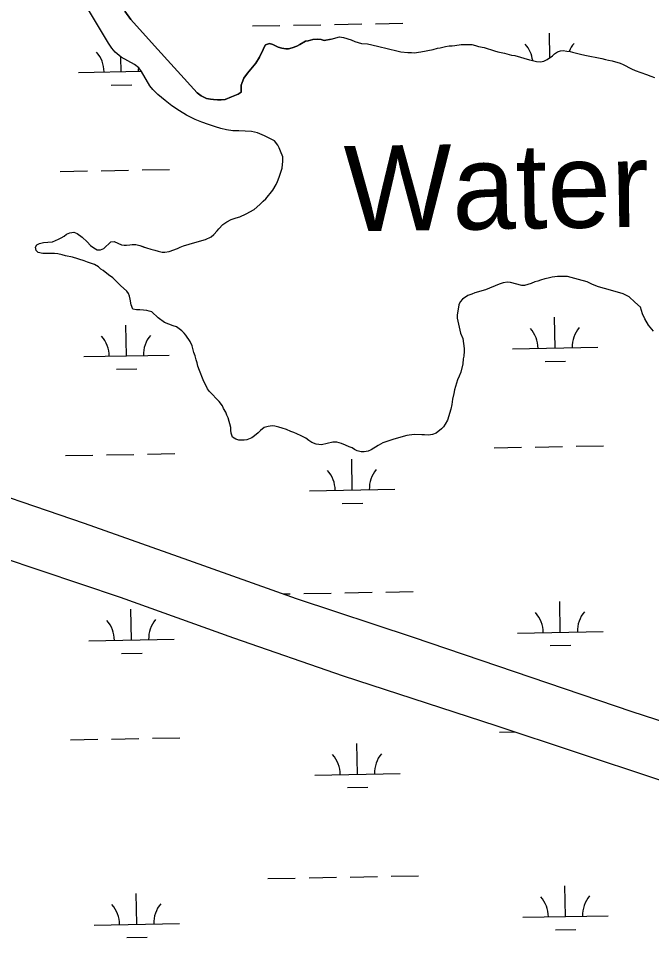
# Model space of a CAD drawing. Extents: x 3957609 to 3995875, y 234277 to 260273.
# Drawn here: x 3983519 to 3984260, y 241597 to 242673 of the extents above; entities that cross this region are included whole.
import ezdxf

# ---------------------------------------------------------------- set-up
doc = ezdxf.new("R2010")
doc.units = 0
for name, color, linetype in [('V-RIVR-IDEN', 7, 'Continuous'), ('V-TOPO-SHOR', 7, 'Continuous'), ('V-WETL-SWMP', 7, 'Continuous')]:
    doc.layers.add(name, color=color, linetype=linetype)

msp = doc.modelspace()

# ---------------------------------------------------------------- linework, layer by layer
at = {"layer": 'V-TOPO-SHOR'}
for points in [[(3983818.555, 242529.578), (3983806.546, 242535.138), (3983798.341, 242538.71), (3983791.341, 242540.487), (3983776.549, 242541.241), (3983769.753, 242541.223), (3983762.356, 242542.398), (3983755.557, 242543.776), (3983749.353, 242545.757), (3983741.151, 242548.731), (3983733.147, 242551.305), (3983725.543, 242554.477), (3983715.535, 242559.644), (3983707.125, 242564.615), (3983698.315, 242570.585), (3983690.301, 242576.755), (3983681.886, 242583.526), (3983675.873, 242589.502), (3983672.26, 242593.889), (3983662.819, 242610.449), (3983659.405, 242615.035), (3983654.598, 242618.817), (3983638.784, 242627.364), (3983631.97, 242633.34), (3983628.159, 242637.925), (3983623.944, 242643.709), (3983593.81, 242694.98)], [(3983779.502, 242586.426), (3983775.91, 242584.216), (3983767.926, 242580.794), (3983760.539, 242577.974), (3983755.946, 242577.362), (3983751.747, 242577.347), (3983746.949, 242577.933), (3983743.551, 242578.123), (3983738.951, 242579.109), (3983732.545, 242582.285), (3983727.741, 242585.47), (3983677.808, 242640.481), (3983650.332, 242671.375), (3983643.107, 242681.347)], [(3983884.806, 242648.536), (3983876.673, 242647.004), (3983873.052, 242647.897), (3983868.53, 242648.485), (3983863.406, 242648.167), (3983857.684, 242646.643), (3983854.674, 242646.031), (3983848.054, 242642.093), (3983844.442, 242640.274), (3983839.023, 242638.148), (3983834.806, 242637.231), (3983831.49, 242637.221), (3983826.968, 242637.81), (3983822.745, 242639.002), (3983816.405, 242642.3), (3983812.485, 242643.19), (3983807.967, 242641.972), (3983806.167, 242639.254), (3983804.971, 242636.235), (3983800.778, 242627.181), (3983796.578, 242620.538), (3983792.674, 242615.702), (3983786.668, 242608.751), (3983782.465, 242602.712), (3983780.37, 242597.582), (3983779.475, 242594.565), (3983779.186, 242590.645), (3983779.502, 242586.426)], [(3983884.806, 242648.536), (3983894.444, 242651.276), (3983899.269, 242650.387), (3983908.018, 242647.7), (3983912.243, 242645.603), (3983920.087, 242643.518), (3983927.322, 242642.937), (3983939.086, 242640.26), (3983951.755, 242636.983), (3983961.706, 242634.902), (3983966.232, 242633.71), (3983974.373, 242632.832), (3983978.893, 242632.844), (3983981.91, 242632.553), (3983989.44, 242633.481), (3984004.202, 242636.238), (3984009.019, 242637.759), (3984012.333, 242638.372), (3984018.358, 242639.897), (3984022.876, 242640.514), (3984026.493, 242640.825), (3984029.505, 242640.835), (3984036.737, 242642.062), (3984041.859, 242642.379), (3984046.08, 242642.394), (3984049.395, 242642.101), (3984053.618, 242641.21), (3984057.239, 242640.014), (3984063.574, 242638.527), (3984075.942, 242634.947), (3984079.562, 242633.753), (3984087.705, 242631.97), (3984095.85, 242629.885), (3984099.469, 242629.293), (3984116.664, 242624.222), (3984120.285, 242623.329), (3984125.11, 242622.438), (3984129.632, 242621.848), (3984133.548, 242622.766), (3984137.459, 242624.584), (3984143.775, 242629.127), (3984146.182, 242631.242), (3984149.489, 242633.663), (3984153.102, 242634.882), (3984156.117, 242635.191), (3984160.641, 242634.3), (3984164.257, 242634.011), (3984167.274, 242633.114), (3984176.623, 242631.034), (3984181.45, 242629.543), (3984201.658, 242625.684), (3984205.881, 242624.793), (3984209.199, 242623.898), (3984213.723, 242623.007), (3984222.773, 242620.323), (3984226.394, 242618.827), (3984236.355, 242613.732), (3984240.58, 242611.938), (3984253.857, 242607.156), (3984258.988, 242605.061), (3984263.213, 242603.568)], [(3983664.611, 242405.532), (3983668.533, 242404.037), (3983673.661, 242402.546), (3983678.486, 242401.354), (3983682.107, 242400.16), (3983686.932, 242399.272), (3983689.947, 242399.28), (3983695.069, 242399.898), (3983705.006, 242403.546), (3983708.014, 242405.061), (3983711.928, 242406.581), (3983725.179, 242410.54), (3983737.526, 242413.892), (3983744.147, 242417.229), (3983747.455, 242419.95), (3983751.358, 242424.181), (3983753.16, 242426.598), (3983757.967, 242431.435), (3983762.479, 242434.766), (3983767.595, 242437.493), (3983773.317, 242439.318), (3983777.835, 242440.539), (3983785.359, 242443.877), (3983794.688, 242449.03), (3983801.301, 242455.078), (3983804.905, 242458.705), (3983808.213, 242461.73), (3983816.321, 242471.699), (3983820.218, 242478.343), (3983821.715, 242481.663), (3983823.808, 242487.094), (3983827.394, 242497.354), (3983828.273, 242505.796), (3983827.957, 242510.617), (3983825.524, 242517.544), (3983824.007, 242521.154), (3983822.188, 242524.466), (3983818.555, 242529.578)], [(3983656.695, 242331.663), (3983652.475, 242332.253), (3983650.65, 242337.674), (3983649.425, 242343.998), (3983648.51, 242347.613), (3983647.295, 242350.623), (3983645.479, 242353.331), (3983637.921, 242360.241), (3983629.154, 242368.953), (3983624.02, 242372.555), (3983617.976, 242377.661), (3983615.258, 242379.16), (3983612.235, 242382.165), (3983607.705, 242384.864), (3983599.56, 242387.553), (3983595.636, 242389.046), (3983582.06, 242393.226), (3983573.616, 242394.707), (3983569.694, 242395.901), (3983564.869, 242397.093), (3983560.949, 242397.682), (3983547.386, 242397.641), (3983541.655, 242398.829), (3983539.538, 242401.236), (3983538.622, 242404.848), (3983540.119, 242407.867), (3983543.431, 242409.385), (3983547.951, 242410.302), (3983553.073, 242410.921), (3983558.496, 242411.238), (3983565.721, 242414.275), (3983568.73, 242415.791), (3983572.34, 242417.913), (3983574.747, 242420.028), (3983578.658, 242421.849), (3983583.479, 242422.467), (3983587.401, 242420.972), (3983593.443, 242416.77), (3983599.188, 242411.062), (3983603.118, 242406.853), (3983606.743, 242404.15), (3983610.669, 242402.055), (3983614.587, 242402.065), (3983618.5, 242403.284), (3983626.918, 242411.146), (3983630.532, 242411.758), (3983639.283, 242407.867), (3983642.3, 242407.273), (3983645.315, 242407.283), (3983648.929, 242407.896), (3983651.942, 242408.207), (3983656.163, 242408.219), (3983660.687, 242407.027), (3983664.611, 242405.532)], [(3984246.847, 242334.96), (3984240.199, 242340.666), (3984233.549, 242346.675), (3984226.607, 242350.271), (3984217.254, 242353.257), (3984204.585, 242356.534), (3984197.646, 242358.623), (3984190.705, 242361.314), (3984184.367, 242364.308), (3984174.108, 242367.292), (3984161.439, 242370.571), (3984156.616, 242370.856), (3984149.684, 242370.835), (3984143.358, 242369.912), (3984138.84, 242368.693), (3984134.924, 242368.079), (3984129.804, 242366.555), (3984126.492, 242365.34), (3984123.179, 242364.425), (3984118.665, 242362.602), (3984110.833, 242360.167), (3984107.821, 242360.159), (3984094.548, 242363.737), (3984090.931, 242364.026), (3984085.809, 242363.106), (3984081.293, 242361.584), (3984065.337, 242354.906), (3984052.99, 242351.553), (3984049.379, 242350.036), (3984044.56, 242348.514), (3984038.545, 242343.974), (3984035.541, 242340.951), (3984034.044, 242337.33), (3984031.971, 242325.568), (3984032.282, 242321.951), (3984036.253, 242304.482)], [(3984036.253, 242304.482), (3984038.684, 242298.16), (3984040.528, 242286.41), (3984040.538, 242283.398), (3984039.952, 242277.366), (3984039.057, 242274.35), (3984038.774, 242268.622), (3984036.393, 242258.668), (3984034.599, 242253.839), (3984032.501, 242249.614), (3984028.919, 242238.149), (3984028.332, 242233.627), (3984026.845, 242226.992), (3984025.958, 242220.96), (3984024.768, 242215.531), (3984020.889, 242202.559), (3984018.192, 242197.728), (3984016.091, 242194.707), (3984013.686, 242192.288), (3984007.674, 242187.447), (3984003.158, 242185.927), (3983998.64, 242185.01), (3983993.815, 242185.297), (3983990.8, 242185.286), (3983981.756, 242185.864), (3983973.32, 242184.631), (3983957.962, 242180.365), (3983945.316, 242176.107), (3983942.305, 242174.592), (3983939.598, 242172.773), (3983931.476, 242167.928), (3983928.164, 242166.41), (3983923.345, 242165.49), (3983919.728, 242165.48), (3983915.204, 242166.672), (3983912.186, 242168.169), (3983909.165, 242169.969), (3983905.845, 242171.466), (3983901.62, 242173.263), (3983896.793, 242175.057), (3983891.361, 242176.849), (3983886.538, 242176.832), (3983873.288, 242173.478), (3983866.955, 242174.362), (3983862.126, 242176.457), (3983858.501, 242178.557), (3983855.179, 242181.26), (3983849.744, 242184.256), (3983844.614, 242186.652), (3983840.993, 242188.147), (3983837.37, 242189.343), (3983832.543, 242191.439), (3983827.413, 242193.231), (3983823.491, 242194.425), (3983818.666, 242195.616), (3983815.651, 242195.907), (3983811.129, 242195.293), (3983806.312, 242193.769), (3983801.8, 242190.441), (3983799.398, 242187.721), (3983794.888, 242184.09), (3983791.88, 242181.971), (3983785.861, 242179.542), (3983782.846, 242178.929), (3983779.532, 242178.919), (3983776.518, 242179.212), (3983773.198, 242180.107), (3983769.272, 242182.806), (3983767.75, 242187.322), (3983767.138, 242190.638), (3983767.128, 242193.951), (3983764.08, 242205.398), (3983762.563, 242208.406), (3983761.346, 242212.019), (3983758.62, 242216.232), (3983757.408, 242219.24), (3983753.775, 242224.354), (3983742.285, 242236.075), (3983739.865, 242239.382), (3983735.011, 242249.616), (3983730.757, 242260.755), (3983728.631, 242265.57), (3983727.716, 242269.789), (3983726.5, 242273.101), (3983725.58, 242277.919), (3983724.062, 242281.833), (3983721.928, 242289.665), (3983719.803, 242294.48), (3983714.658, 242302), (3983712.538, 242304.404), (3983709.819, 242307.11), (3983703.777, 242311.611), (3983699.855, 242312.805), (3983689.595, 242316.692), (3983682.044, 242322.095), (3983674.788, 242329.308), (3983671.771, 242330.203), (3983668.754, 242330.797), (3983665.137, 242331.086), (3983660.613, 242331.675), (3983656.695, 242331.663)], [(3984262.08, 242306.512), (3984256.061, 242313.888), (3984251.842, 242321.071), (3984249.026, 242327.057), (3984246.847, 242334.96)], [(3982697.627, 242304.773), (3982837.074, 242257.231), (3983023.329, 242196.837), (3983188.168, 242145.574), (3983498.266, 242042.186), (3983637.911, 241995.443), (3983770.564, 241947.679), (3983898.611, 241903.099), (3984077.263, 241845.282), (3984265.521, 241782.697), (3984455.375, 241721.914), (3984625.426, 241665.672), (3984787.079, 241611.599)], [(3983435.776, 242136.521), (3983595.43, 242081.846), (3983717.875, 242038.648), (3983843.725, 241993.661), (3983980.765, 241948.509), (3984236.449, 241861.547), (3984346.081, 241825.903)]]:
    msp.add_lwpolyline(points, dxfattribs=at)
at = {"layer": 'V-WETL-SWMP'}
for p, q in [((3983792.605, 242663.94), (3983824.6, 242664.522)), ((3983840.597, 242664.813), (3983872.592, 242665.395)), ((3983888.589, 242665.686), (3983920.584, 242666.267)), ((3983936.581, 242666.558), (3983968.576, 242667.14)), ((3984140.652, 242626.88), (3984140.131, 242655.515)), ((3983638.961, 242610.396), (3983638.65, 242627.48)), ((3983588.969, 242609.487), (3983662.538, 242610.825)), ((3983627.243, 242594.75), (3983651.239, 242595.186)), ((3983567.664, 242493.649), (3983599.658, 242494.23)), ((3983615.656, 242494.521), (3983647.65, 242495.103)), ((3983663.648, 242495.394), (3983695.642, 242495.976)), ((3984146.834, 242286.901), (3984146.179, 242322.895)), ((3983645.009, 242277.776), (3983644.354, 242313.77)), ((3984096.842, 242285.992), (3984196.826, 242287.81)), ((3983595.017, 242276.867), (3983695.001, 242278.685)), ((3984135.116, 242271.254), (3984159.112, 242271.691)), ((3983633.291, 242262.13), (3983657.287, 242262.566)), ((3984075.537, 242170.153), (3984107.531, 242170.735)), ((3984123.529, 242171.026), (3984155.523, 242171.608)), ((3984171.521, 242171.899), (3984203.515, 242172.48)), ((3983573.712, 242161.029), (3983605.706, 242161.61)), ((3983621.704, 242161.901), (3983653.698, 242162.483)), ((3983669.696, 242162.774), (3983701.69, 242163.356)), ((3983909.344, 242120.694), (3983908.69, 242156.688)), ((3983859.353, 242119.785), (3983959.336, 242121.603)), ((3983897.627, 242105.047), (3983921.623, 242105.484)), ((3983498.267, 242042.187), (3983637.912, 241995.443)), ((3983828.42, 241999.132), (3983836.696, 241999.282)), ((3983852.693, 241999.573), (3983884.688, 242000.155)), ((3983900.685, 242000.446), (3983932.68, 242001.027)), ((3983948.677, 242001.318), (3983980.672, 242001.9)), ((3983637.912, 241995.443), (3983770.565, 241947.679)), ((3984152.882, 241954.281), (3984152.228, 241990.275)), ((3983651.057, 241945.156), (3983650.402, 241981.15)), ((3984102.89, 241953.372), (3984202.874, 241955.19)), ((3983601.065, 241944.247), (3983701.049, 241946.065)), ((3983770.565, 241947.679), (3983898.611, 241903.099)), ((3984141.165, 241938.634), (3984165.161, 241939.071)), ((3983639.339, 241929.51), (3983663.335, 241929.946)), ((3983898.611, 241903.099), (3984077.262, 241845.282)), ((3984077.262, 241845.282), (3984265.521, 241782.697)), ((3984081.585, 241837.533), (3984099.586, 241837.861)), ((3983579.76, 241828.409), (3983611.754, 241828.99)), ((3983627.752, 241829.281), (3983659.746, 241829.863)), ((3983675.744, 241830.154), (3983707.738, 241830.736)), ((3983915.392, 241788.074), (3983914.738, 241824.068)), ((3983865.401, 241787.165), (3983965.384, 241788.983)), ((3983903.675, 241772.427), (3983927.671, 241772.864)), ((3983810.749, 241666.08), (3983842.744, 241666.662)), ((3983858.741, 241666.953), (3983890.736, 241667.535)), ((3983906.733, 241667.826), (3983938.728, 241668.407)), ((3983954.725, 241668.698), (3983986.72, 241669.28)), ((3984158.93, 241621.661), (3984158.275, 241657.655)), ((3983657.105, 241612.536), (3983656.45, 241648.53)), ((3984108.938, 241620.752), (3984208.922, 241622.57)), ((3983607.113, 241611.627), (3983707.097, 241613.445)), ((3984147.212, 241606.014), (3984171.208, 241606.451)), ((3983645.387, 241596.889), (3983669.383, 241597.326))]:
    msp.add_line(p, q, dxfattribs=at)
for points in [[(3983660.687, 242407.028), (3983668.533, 242404.038), (3983673.661, 242402.546), (3983678.487, 242401.355), (3983682.108, 242400.16), (3983686.933, 242399.271), (3983689.947, 242399.28), (3983695.069, 242399.898), (3983705.005, 242403.545), (3983708.014, 242405.062), (3983711.928, 242406.58), (3983725.178, 242410.539), (3983737.526, 242413.892), (3983744.147, 242417.228), (3983747.454, 242419.95), (3983751.359, 242424.182), (3983753.16, 242426.599), (3983757.968, 242431.436), (3983762.479, 242434.765), (3983767.595, 242437.493), (3983773.316, 242439.319), (3983777.834, 242440.538), (3983785.359, 242443.877), (3983794.687, 242449.029), (3983801.3, 242455.077), (3983804.906, 242458.705), (3983808.212, 242461.729), (3983816.32, 242471.7), (3983820.218, 242478.343), (3983821.715, 242481.663), (3983823.808, 242487.095), (3983827.394, 242497.354), (3983828.273, 242505.796), (3983827.957, 242510.618), (3983825.524, 242517.543), (3983824.006, 242521.155), (3983822.188, 242524.465), (3983818.555, 242529.578), (3983806.546, 242535.138), (3983798.341, 242538.71), (3983791.341, 242540.488), (3983776.549, 242541.242), (3983769.754, 242541.222), (3983762.355, 242542.398), (3983755.556, 242543.777), (3983749.354, 242545.757), (3983741.151, 242548.73), (3983733.148, 242551.304), (3983725.544, 242554.478), (3983715.535, 242559.644), (3983707.126, 242564.615), (3983698.314, 242570.584), (3983690.301, 242576.756), (3983681.886, 242583.526), (3983675.872, 242589.503), (3983672.261, 242593.889), (3983662.818, 242610.449), (3983659.406, 242615.035), (3983654.598, 242618.818), (3983638.783, 242627.364), (3983631.97, 242633.339), (3983628.158, 242637.925), (3983623.944, 242643.708), (3983593.809, 242694.981)], [(3983643.108, 242681.346), (3983650.333, 242671.375), (3983677.808, 242640.48), (3983727.74, 242585.47), (3983732.546, 242582.286), (3983738.951, 242579.108), (3983743.551, 242578.123), (3983746.949, 242577.933), (3983751.748, 242577.348), (3983755.945, 242577.361), (3983760.54, 242577.974), (3983767.926, 242580.795), (3983775.91, 242584.217), (3983779.501, 242586.426), (3983779.187, 242590.645), (3983779.476, 242594.564), (3983780.371, 242597.581), (3983782.466, 242602.711), (3983786.667, 242608.752), (3983792.674, 242615.703), (3983796.578, 242620.537), (3983800.778, 242627.181)], [(3983800.778, 242627.181), (3983804.97, 242636.236), (3983806.166, 242639.254), (3983807.966, 242641.972), (3983812.484, 242643.191), (3983816.405, 242642.299), (3983822.745, 242639.003), (3983826.968, 242637.81), (3983831.491, 242637.221), (3983834.806, 242637.231), (3983839.023, 242638.148), (3983844.442, 242640.274), (3983848.054, 242642.093), (3983854.673, 242646.032), (3983857.685, 242646.644), (3983863.407, 242648.168), (3983868.53, 242648.485), (3983873.053, 242647.896), (3983876.673, 242647.003), (3983884.806, 242648.535), (3983894.443, 242651.276), (3983899.268, 242650.387), (3983908.017, 242647.701), (3983912.243, 242645.604), (3983920.086, 242643.518), (3983927.322, 242642.937), (3983939.085, 242640.26), (3983951.754, 242636.983), (3983961.707, 242634.903), (3983966.232, 242633.711), (3983974.373, 242632.832), (3983978.894, 242632.845), (3983981.909, 242632.553), (3983989.441, 242633.48), (3984004.202, 242636.238), (3984009.02, 242637.759), (3984012.333, 242638.372), (3984018.357, 242639.897), (3984022.876, 242640.514), (3984026.492, 242640.826), (3984029.506, 242640.835), (3984036.736, 242642.063), (3984041.859, 242642.38), (3984046.079, 242642.393), (3984049.396, 242642.101), (3984053.618, 242641.21), (3984057.239, 242640.015), (3984063.573, 242638.528), (3984075.941, 242634.948), (3984079.562, 242633.754), (3984087.705, 242631.97), (3984095.85, 242629.885), (3984099.469, 242629.293), (3984116.664, 242624.221), (3984120.284, 242623.328), (3984125.109, 242622.438), (3984129.632, 242621.849), (3984133.548, 242622.765), (3984137.46, 242624.585), (3984143.776, 242629.126), (3984146.181, 242631.243), (3984149.489, 242633.664), (3984153.103, 242634.881), (3984156.116, 242635.191), (3984160.64, 242634.301), (3984164.257, 242634.011), (3984167.274, 242633.115), (3984176.624, 242631.034), (3984181.451, 242629.542), (3984201.658, 242625.684), (3984205.88, 242624.793), (3984209.198, 242623.899), (3984213.722, 242623.008), (3984222.772, 242620.323), (3984226.394, 242618.827), (3984236.356, 242613.733), (3984240.581, 242611.938), (3984253.858, 242607.155), (3984258.988, 242605.061), (3984263.212, 242603.567)], [(3983827.413, 242193.231), (3983823.491, 242194.425), (3983818.665, 242195.616), (3983815.65, 242195.908), (3983811.13, 242195.292), (3983806.312, 242193.77), (3983801.801, 242190.441), (3983799.398, 242187.721), (3983794.888, 242184.09), (3983791.88, 242181.971), (3983785.86, 242179.542), (3983782.847, 242178.93), (3983779.532, 242178.92), (3983776.517, 242179.212), (3983773.199, 242180.106), (3983769.272, 242182.807), (3983767.751, 242187.323), (3983767.138, 242190.637), (3983767.128, 242193.952), (3983764.08, 242205.397), (3983762.563, 242208.406), (3983761.347, 242212.019), (3983758.621, 242216.231), (3983757.407, 242219.241), (3983753.774, 242224.354), (3983742.285, 242236.074), (3983739.864, 242239.383), (3983735.01, 242249.616), (3983730.757, 242260.755), (3983728.632, 242265.571), (3983727.715, 242269.788), (3983726.499, 242273.1), (3983725.58, 242277.92), (3983724.062, 242281.834), (3983721.928, 242289.664), (3983719.803, 242294.48), (3983714.657, 242301.999), (3983712.539, 242304.404), (3983709.819, 242307.109), (3983703.777, 242311.612), (3983699.855, 242312.805), (3983689.595, 242316.693), (3983682.043, 242322.095), (3983674.788, 242329.307), (3983671.771, 242330.202), (3983668.755, 242330.796), (3983665.137, 242331.086), (3983660.614, 242331.675), (3983656.696, 242331.663), (3983652.474, 242332.253), (3983650.649, 242337.673), (3983649.425, 242343.999), (3983648.509, 242347.613), (3983647.295, 242350.624), (3983645.478, 242353.331), (3983637.922, 242360.24), (3983629.154, 242368.954), (3983624.02, 242372.556), (3983617.976, 242377.661), (3983615.259, 242379.16), (3983612.235, 242382.165), (3983607.706, 242384.864), (3983599.56, 242387.552), (3983595.637, 242389.047), (3983582.061, 242393.226), (3983573.617, 242394.707), (3983569.695, 242395.901), (3983564.869, 242397.092), (3983560.949, 242397.683), (3983547.385, 242397.642), (3983541.655, 242398.83), (3983539.538, 242401.235), (3983538.622, 242404.849), (3983540.12, 242407.868), (3983543.431, 242409.385), (3983547.95, 242410.303), (3983553.072, 242410.921), (3983558.496, 242411.239), (3983565.721, 242414.275), (3983568.73, 242415.791), (3983572.341, 242417.912), (3983574.746, 242420.029), (3983578.658, 242421.849), (3983583.479, 242422.467), (3983587.402, 242420.972), (3983593.443, 242416.77), (3983599.187, 242411.061), (3983603.118, 242406.853), (3983606.743, 242404.151), (3983610.668, 242402.054), (3983614.586, 242402.065), (3983618.501, 242403.283), (3983626.917, 242411.145), (3983630.532, 242411.759), (3983639.284, 242407.867), (3983642.3, 242407.273), (3983645.314, 242407.283), (3983648.929, 242407.896), (3983651.943, 242408.207), (3983656.162, 242408.22), (3983660.687, 242407.028)], [(3984262.08, 242306.511), (3984256.061, 242313.888), (3984251.843, 242321.07), (3984249.026, 242327.057), (3984246.847, 242334.961), (3984240.199, 242340.667), (3984233.549, 242346.675), (3984226.606, 242350.271), (3984217.253, 242353.257), (3984204.584, 242356.534), (3984197.645, 242358.623), (3984190.705, 242361.315), (3984184.366, 242364.309), (3984174.109, 242367.292), (3984161.44, 242370.57), (3984156.616, 242370.856), (3984149.684, 242370.835), (3984143.357, 242369.912), (3984138.84, 242368.692), (3984134.923, 242368.078), (3984129.804, 242366.555), (3984126.492, 242365.34), (3984123.179, 242364.425), (3984118.664, 242362.603), (3984110.834, 242360.168), (3984107.82, 242360.159), (3984094.547, 242363.736), (3984090.93, 242364.026), (3984085.809, 242363.106), (3984081.292, 242361.585), (3984065.337, 242354.906), (3984052.99, 242351.553), (3984049.378, 242350.035), (3984044.56, 242348.513), (3984038.545, 242343.974), (3984035.54, 242340.951), (3984034.044, 242337.329), (3984031.97, 242325.568), (3984032.282, 242321.952), (3984036.254, 242304.482), (3984038.684, 242298.16), (3984040.528, 242286.411), (3984040.537, 242283.397), (3984039.953, 242277.367), (3984039.058, 242274.35), (3984038.774, 242268.622), (3984036.393, 242258.668), (3984034.599, 242253.84), (3984032.502, 242249.614), (3984028.92, 242238.15), (3984028.331, 242233.627), (3984026.844, 242226.991), (3984025.958, 242220.96), (3984024.769, 242215.531), (3984020.89, 242202.559), (3984018.192, 242197.728), (3984016.091, 242194.708), (3984013.687, 242192.289), (3984007.673, 242187.448), (3984003.157, 242185.928), (3983998.639, 242185.01), (3983993.815, 242185.297), (3983990.801, 242185.287), (3983981.757, 242185.863), (3983973.321, 242184.632), (3983957.962, 242180.365), (3983945.316, 242176.107), (3983942.306, 242174.591), (3983939.599, 242172.774), (3983931.476, 242167.927), (3983928.165, 242166.41), (3983923.345, 242165.491), (3983919.728, 242165.48), (3983915.204, 242166.672), (3983912.185, 242168.17), (3983909.165, 242169.969), (3983905.845, 242171.466), (3983901.62, 242173.262), (3983896.792, 242175.056), (3983891.361, 242176.848), (3983886.539, 242176.833), (3983873.287, 242173.477), (3983866.955, 242174.362), (3983862.126, 242176.457), (3983858.502, 242178.556), (3983855.179, 242181.259), (3983849.744, 242184.257), (3983844.613, 242186.652), (3983840.992, 242188.148), (3983837.371, 242189.343), (3983832.542, 242191.438), (3983827.413, 242193.231)], [(3983435.776, 242136.522), (3983595.43, 242081.845), (3983717.875, 242038.647), (3983843.724, 241993.661), (3983980.764, 241948.508), (3984236.449, 241861.546), (3984346.08, 241825.904)]]:
    msp.add_lwpolyline(points, dxfattribs=at)
for centre, start, end in [((3984085.543, 242618.991), 6.994045, 41.813537), ((3984196.011, 242621), 140.269876, 158.200616), ((3983583.718, 242609.867), 0.269879, 41.813537), ((3983694.186, 242611.875), 174.468446, 181.813534), ((3984091.592, 242286.371), 0.269879, 41.813537), ((3984202.059, 242288.38), 140.269876, 181.813534), ((3983589.766, 242277.247), 0.269879, 41.813537), ((3983700.234, 242279.255), 140.269876, 181.813534), ((3983854.102, 242120.164), 0.269879, 41.813537), ((3983964.57, 242122.173), 140.269876, 181.813534), ((3984097.64, 241953.751), 0.269879, 41.813537), ((3984208.107, 241955.76), 140.269876, 181.813534), ((3983595.814, 241944.627), 0.269879, 41.813537), ((3983706.282, 241946.635), 140.269876, 181.813534), ((3983860.15, 241787.544), 0.269879, 41.813537), ((3983970.617, 241789.553), 140.269876, 181.813534), ((3984103.687, 241621.131), 0.269879, 41.813537), ((3984214.155, 241623.14), 140.269876, 181.813534), ((3983601.862, 241612.007), 0.269879, 41.813537), ((3983712.33, 241614.015), 140.269876, 181.813534)]:
    msp.add_arc(centre, 35.246, start, end, dxfattribs=at)

# ---------------------------------------------------------------- texts
at = {"layer": 'V-RIVR-IDEN'}
msp.add_text('Water', height=99.9998, rotation=0.902342, dxfattribs=at).set_placement((3983900.632, 242423.34))

doc.saveas('drawing.dxf')
